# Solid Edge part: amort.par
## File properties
Title: Amort haagisele (standard)
Author: Kadik
Template: Normal.par
Last saved by: Kadik
Revision: 13
Application: Solid Edge
Document Number: 502600
Density: 7860,000 kg/m^3
Accuracy: 0,99
Coef. of Thermal Exp: 0.0
Thermal Conductivity: 0.0
Specific Heat: 0.0
Modulus of Elasticity: 0.0
Poission's Ratio: 0.0
Yield Stress: 0.0
Ultimate Stress: 0.0
Elongation: 0.0
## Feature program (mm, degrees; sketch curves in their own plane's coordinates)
sketch for "unnamed Protrusion 1" plane through (0, 0, 0) normal (0, 0, 1) x-axis (1, 0, 0)
  circle centre (0, 0) radius 20
extrude "unnamed Protrusion 1" add finite 230 along +normal
sketch for "ExtrudedProtrusion_2" plane through (0, 0, 230) normal (0, 0, 1) x-axis (-1, 0, 0)
  circle centre (0, 0) radius 17.5
extrude "ExtrudedProtrusion_2" add finite 65 along +normal
sketch for "ExtrudedProtrusion_5" plane through (0, 0, 0) normal (1, 0, 0) x-axis (0, 1, 0)
  circle centre (0, -16) radius 16.0754
extrude "ExtrudedProtrusion_5" add finite 35 symmetric
sketch for "Hole_1" plane through (17.5, 0, -16.0377) normal (1, 0, 0) x-axis (0, 0, 1)
  hole centre (0.0377, 0) bore radius 6
hole "Hole_1" diameter 12 through
sketch for "ExtrudedProtrusion_9" plane through (0, 0, 0) normal (1, 0, 0) x-axis (0, 1, 0)
extrude "ExtrudedProtrusion_9" add finite 35 symmetric
sketch for "Hole_3" plane through (17.5, 0, 306) normal (1, 0, 0) x-axis (0, 0, -1)
hole "Hole_3" diameter 12 through
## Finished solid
Body 1: solid body, 14 faces, 23 edges, 10 vertices.
  Faces by surface: plane 8, cylinder 6
  Edges by curve: circle 13, line 6, intersection 4
Bounding box of the edges (mm): 40.000 x 40.000 x 359.386, from (-20, -20, -32.0754) to (20, 20, 327.3103).
Cylindrical faces by radius (mm): R6 x2, R16.0754 x1, R16.3103 x1, R17.5 x1, R20 x1
Planar faces by outward normal: +x 2, +z 3, -x 2, -z 1
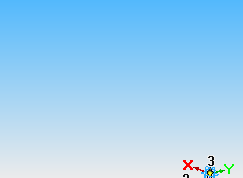
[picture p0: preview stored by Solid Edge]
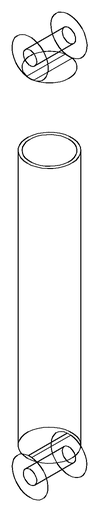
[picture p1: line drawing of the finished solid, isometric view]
